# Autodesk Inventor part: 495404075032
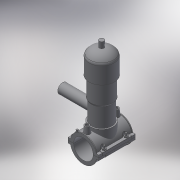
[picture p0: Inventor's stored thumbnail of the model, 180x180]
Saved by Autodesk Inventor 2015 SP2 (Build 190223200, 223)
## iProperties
Created: 2017-07
Part Number: 495404075032
Material: Generic
Description: PLASSON TAPPING VALVE 75-32
Document SubType Name: Modeling
Designer: KIM
Density: 1 g/cm^3
Appearance: Default
Author: KIM
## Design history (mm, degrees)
derived "495404-4954S4.ipt"
feature "Solid1::495404-4954S4.ipt"
feature "Solid2::495404-4954S4.ipt"
tag "TaggingFeature1"
body "Solid1"
body "Solid2"
other parameters: "d_" = 75, "B_" = 117, "H_" = 126, "L_" = 118, "d_t" = 6, "d_1" = 32, "H_1" = 46, "H_2" = 244, "d148" = 1.125, "d160" = 1.125, "d169" = 3, "d192" = 6.8, "d228" = 25.6, "d0" = 75, "d2" = 117, "d3" = 18.75, "d4" = 118, "d5" = 0, "d6" = 0.1, "d8" = 0, "d19" = 6, "d20" = 6, "d21" = 70.8, "d23" = 0, "d24" = 35.4, "d26" = 0, "d27" = 3, "d28" = 3, "d29" = 3, "d30" = 25, "d31" = 6, "d32" = 0, "d33" = 0, "d34" = 0.6, "d40" = 50.7, "d47" = 94.75, "d70" = 15, "d72" = 0, "d73" = 6, "d75" = 5, "d76" = 0, "d77" = 3.75, "d78" = 67.5, "d79" = 15, "d80" = 47.2, "d82" = 5 deg, "d84" = 4, "d85" = 14, "d86" = 0, "d87" = 3, "d88" = 0, "d89" = 1, "d90" = 1, "d91" = 94.4, "d92" = 0, "d93" = 0.5, "d94" = 39.47368, "d96" = 100.425, "d97" = 2.36, "d98" = 0, "d120" = 140 deg, "d121" = 24.228, "d122" = 20 deg, "d123" = 195, "d124" = 58.5, "d126" = 0, "d143" = 77.25, "d145" = 17.30769, "d149" = 1.125, "d150" = 19.03846, "d153" = 118, "d154" = 0, "d156" = 48.75, "d157" = 160 deg, "d159" = 4.5, "d161" = 1.125, "d162" = 70.8, "d163" = 0, "d164" = 37.5, "d167" = 7.5, "d168" = 47.56098, "d170" = 3, "d172" = 0, "d173" = 1, "d175" = 37.5, "d176" = 20 deg, "d177" = 5.25, "d178" = 22.5, "d180" = 0, "d183" = 9, "d184" = 4.2, "d185" = 38.35, "d186" = 38.35, "d187" = 48.75, "d188" = 6.75, "d189" = 5.25, "d190" = 0, "d191" = 73.125, "d193" = 6.8, "d194" = 2.95, "d195" = 90 deg, "d197" = 0, "d199" = 0, "d205" = 14.64, "d206" = 81.33333, "d207" = 244, "d208" = 224.48, "d209" = 207.4, "d210" = 200.08, "d211" = 146.4, "d212" = 85.4, "d213" = 65.88, "d214" = 73.2, "d216" = 19.52, "d217" = 70.76, "d218" = 80.52, "d220" = 75, "d222" = 0, "d223" = 97.5, "d224" = 126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
